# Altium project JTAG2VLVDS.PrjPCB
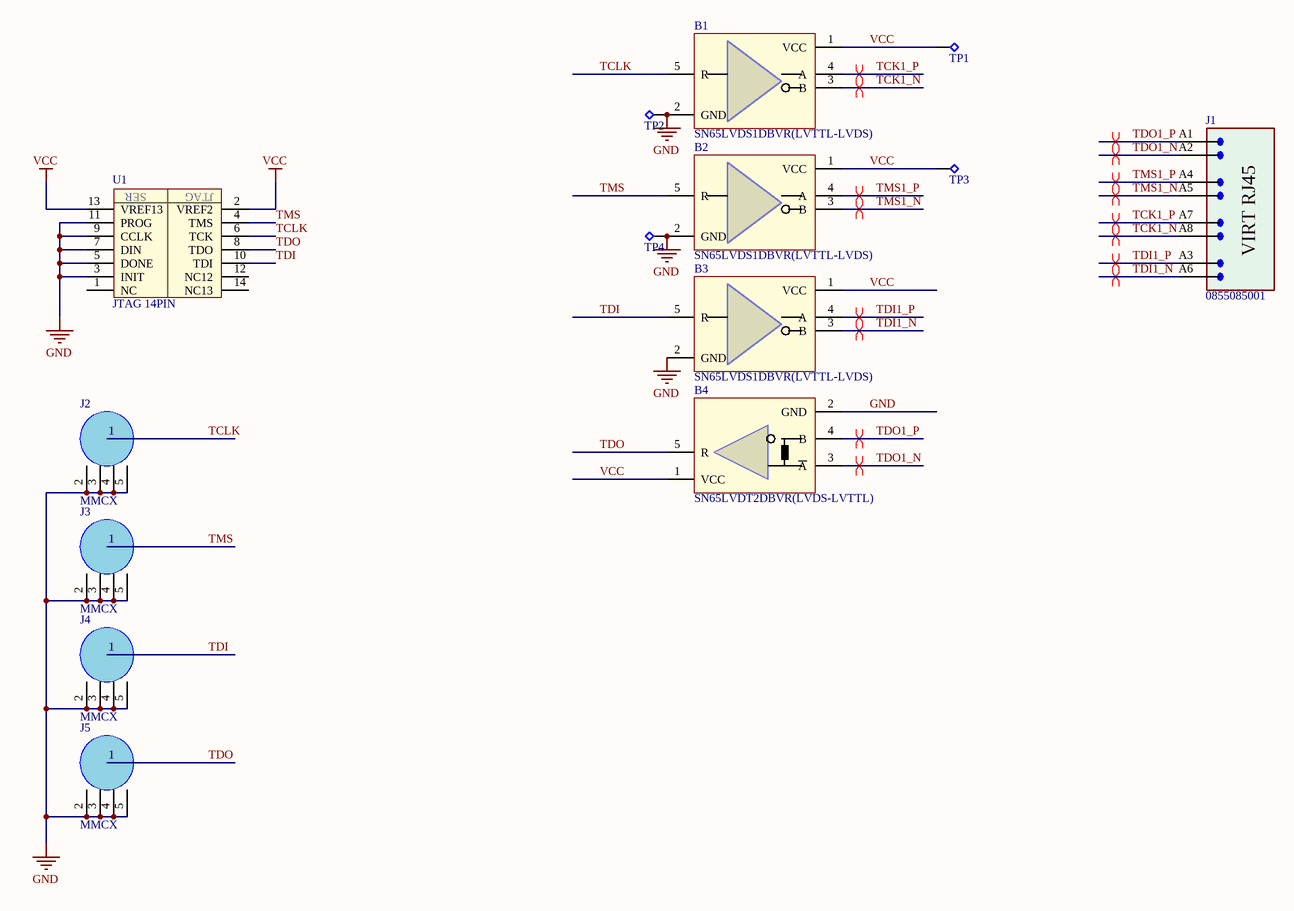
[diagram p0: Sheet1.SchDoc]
1 sheet, 14 parts. Net scope: global (net labels, ports and power ports of the same name join across sheets).
Board file: PCB1.PcbDoc

## Sheet Sheet1.SchDoc
size A0

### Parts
B1  SN65LVDS1DBVR(LVTTL-LVDS)  [SOT23_5PIN]
B2  SN65LVDS1DBVR(LVTTL-LVDS)  [SOT23_5PIN]
B3  SN65LVDS1DBVR(LVTTL-LVDS)  [SOT23_5PIN]
B4  SN65LVDT2DBVR(LVDS-LVTTL)  [SOT23_5PIN]
J1  0855085001  [VIRT RJ45]
J2  MMCX  [MMCX_VERTICAL_THROUGH_HOLE]
J3  MMCX  [MMCX_VERTICAL_THROUGH_HOLE]
J4  MMCX  [MMCX_VERTICAL_THROUGH_HOLE]
J5  MMCX  [MMCX_VERTICAL_THROUGH_HOLE]
TP1  TP 0.5mm  [SP2.0]  (value not drawn)  (no BOM)
TP2  TP 2.0mm  [SP2.0]  (value not drawn)  (no BOM)
TP3  TP 0.5mm  [SP2.0]  (value not drawn)  (no BOM)
TP4  TP 0.5mm  [SP2.0]  (value not drawn)  (no BOM)
U1  JTAG 14PIN  [JTAG_14PIN_2MM_VERT]

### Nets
GND: B1.2(GND) B2.2(GND) B3.2(GND) B4.2(GND) J2.2 J2.3 J2.4 J2.5 J3.2 J3.3 J3.4 J3.5 J4.2 J4.3 J4.4 J4.5 J5.2 J5.3 J5.4 J5.5 TP2.1 TP4.1 U1.3(INIT) U1.5(DONE) U1.7(DIN) U1.9(CCLK) U1.11(PROG)
VCC: B1.1(VCC) B2.1(VCC) B3.1(VCC) B4.1(VCC) TP1.1 TP3.1 U1.2(VREF2) U1.13(VREF13)
TCK1_N: B1.3(B) J1.A8
TCK1_P: B1.4(A) J1.A7
TCLK: B1.5(R) J2.1 U1.6(TCK)
TDI: B3.5(R) J4.1 U1.10(TDI)
TDI1_N: B3.3(B) J1.A6
TDI1_P: B3.4(A) J1.A3
TDO: B4.5(R) J5.1 U1.8(TDO)
TDO1_N: B4.3(~{A}) J1.A2
TDO1_P: B4.4(B) J1.A1
TMS: B2.5(R) J3.1 U1.4(TMS)
TMS1_N: B2.3(B) J1.A5
TMS1_P: B2.4(A) J1.A4

Not connected (* = marked no-connect by the designer): U1 1(NC) 12(NC12) 14(NC13)

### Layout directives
differential pair: TCK1_N, TCK1_P, TDI1_N, TDI1_P, TDO1_N, TDO1_P, TMS1_N, TMS1_P

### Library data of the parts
B1-B3 = SN65LVDS1DBVR(LVTTL-LVDS): IC HIGH DIFF LINE DRIVER SOT23-5; Manufacturer: Texas Instruments
B4 = SN65LVDT2DBVR(LVDS-LVTTL): IC DIFF LINE RECEIVER SOT-23-5; Manufacturer: Texas Instruments
J1 = VIRT RJ45 CONN: CONN MOD JACK 8P8C R/A SHIELDED; Manufacturer: Molex, LLC; Tech: Through Hole, virtcal
J2-J5 = MMCX: CONN MMCX JACK STR 50 OHM PCB; Manufacturer: Molex, LLC; Manufacturer part #: 0734151471
TP1-TP4 = ELE-TP0.5S: Test Point 0.5mm Slim; Sort: 610; Tech: THDW
U1 = JTAG 14PIN: CONN HEADER 14POS 2MM GOLD DIP; Manufacturer: Hirose Electric Co Ltd; Manufacturer part #: A3C-14P-2DSA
